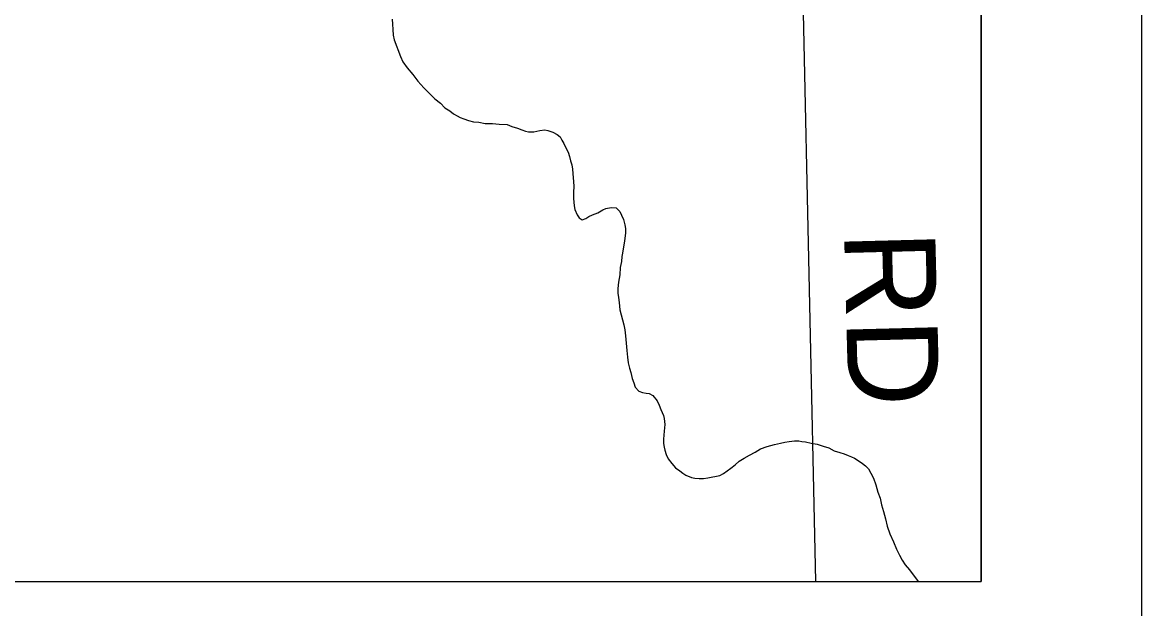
# Model space of a CAD drawing. Extents: x -59 to 82, y -3 to 49.
# Drawn here: x -48.696 to -47.998, y 42.474 to 42.84 of the extents above; entities that cross this region are included whole.
import ezdxf

# ---------------------------------------------------------------- set-up
doc = ezdxf.new("R2010")
doc.units = 0
for name, color, linetype in [('GM_X_Corporation', 7, 'Continuous'), ('GM_X_County_Road', 7, 'Continuous'), ('GM_X_County_Road_Text', 7, 'Continuous'), ('GM_X_Minor_River', 7, 'Continuous'), ('SH_Data', 7, 'Continuous')]:
    doc.layers.add(name, color=color, linetype=linetype)

msp = doc.modelspace()

# ---------------------------------------------------------------- linework, layer by layer
at = {"layer": 'GM_X_Corporation'}
for p, q in [((-48.09799, 42.49125), (-48.09799, 49.29125)), ((-48.09799, 42.49125), (-48.09799, 46.29445)), ((-54.89799, 42.49125), (-48.09799, 42.49125)), ((-49.66963, 42.49125), (-48.09799, 42.49125))]:
    msp.add_line(p, q, dxfattribs=at)
at = {"layer": 'GM_X_County_Road'}
msp.add_line((-48.22596, 43.60749), (-48.20125, 42.49125), dxfattribs=at)
at = {"layer": 'GM_X_Minor_River'}
for p, q in [((-48.46521, 42.84174), (-48.46518, 42.83869)), ((-48.46518, 42.83869), (-48.46478, 42.83527)), ((-48.46478, 42.83527), (-48.46475, 42.83185)), ((-48.46475, 42.83185), (-48.46397, 42.82882)), ((-48.46397, 42.82882), (-48.46009, 42.81858)), ((-48.46009, 42.81858), (-48.45854, 42.81517)), ((-48.45854, 42.81517), (-48.45585, 42.81139)), ((-48.45585, 42.81139), (-48.4524, 42.80723)), ((-48.4524, 42.80723), (-48.44933, 42.80307)), ((-48.44933, 42.80307), (-48.4455, 42.79891)), ((-48.4455, 42.79891), (-48.44205, 42.79552)), ((-48.44205, 42.79552), (-48.43861, 42.79212)), ((-48.43861, 42.79212), (-48.43517, 42.78948)), ((-48.43517, 42.78948), (-48.43249, 42.78646)), ((-48.43249, 42.78646), (-48.42943, 42.78458)), ((-48.42943, 42.78458), (-48.42714, 42.78269)), ((-48.42714, 42.78269), (-48.42485, 42.78157)), ((-48.42485, 42.78157), (-48.42295, 42.78044)), ((-48.42295, 42.78044), (-48.42066, 42.7797)), ((-48.42066, 42.7797), (-48.41762, 42.77858)), ((-48.41762, 42.77858), (-48.41457, 42.77784)), ((-48.41457, 42.77784), (-48.41115, 42.77748)), ((-48.41115, 42.77748), (-48.40735, 42.77675)), ((-48.40735, 42.77675), (-48.40279, 42.77678)), ((-48.40279, 42.77678), (-48.39861, 42.77643)), ((-48.39861, 42.77643), (-48.39367, 42.77609)), ((-48.39367, 42.77609), (-48.39063, 42.77497)), ((-48.39063, 42.77497), (-48.3872, 42.77385)), ((-48.3872, 42.77385), (-48.38453, 42.77273)), ((-48.38453, 42.77273), (-48.38225, 42.77198)), ((-48.37693, 42.77164), (-48.37314, 42.77243)), ((-48.37314, 42.77243), (-48.3701, 42.77283)), ((-48.3701, 42.77283), (-48.3682, 42.77246)), ((-48.3682, 42.77246), (-48.36516, 42.77134)), ((-48.38225, 42.77198), (-48.38035, 42.77162)), ((-48.38035, 42.77162), (-48.37693, 42.77164)), ((-48.36516, 42.77134), (-48.36249, 42.76984)), ((-48.36249, 42.76984), (-48.36058, 42.76834)), ((-48.36058, 42.76834), (-48.35942, 42.76644)), ((-48.35942, 42.76644), (-48.35826, 42.76417)), ((-48.35826, 42.76417), (-48.35672, 42.76114)), ((-48.35672, 42.76114), (-48.35556, 42.75887)), ((-48.35556, 42.75887), (-48.35478, 42.75621)), ((-48.35478, 42.75621), (-48.354, 42.75355)), ((-48.354, 42.75355), (-48.35322, 42.7509)), ((-48.35322, 42.7509), (-48.35282, 42.74824)), ((-48.35282, 42.74824), (-48.35197, 42.7376)), ((-48.35197, 42.7376), (-48.35232, 42.7338)), ((-48.35232, 42.7338), (-48.35229, 42.72999)), ((-48.35229, 42.72999), (-48.35188, 42.72543)), ((-48.35188, 42.72543), (-48.35148, 42.72316)), ((-48.33401, 42.7229), (-48.33212, 42.72367)), ((-48.33212, 42.72367), (-48.32871, 42.72446)), ((-48.32871, 42.72446), (-48.32567, 42.7241)), ((-48.32567, 42.7241), (-48.32337, 42.72183)), ((-48.35148, 42.72316), (-48.34993, 42.71975)), ((-48.34993, 42.71975), (-48.34878, 42.71785)), ((-48.34878, 42.71785), (-48.34687, 42.71673)), ((-48.34687, 42.71673), (-48.3446, 42.7175)), ((-48.3446, 42.7175), (-48.34271, 42.71866)), ((-48.34271, 42.71866), (-48.34044, 42.71981)), ((-48.34044, 42.71981), (-48.33703, 42.72098)), ((-48.33703, 42.72098), (-48.33401, 42.7229)), ((-48.32337, 42.72183), (-48.32221, 42.71956)), ((-48.32221, 42.71956), (-48.32105, 42.71691)), ((-48.32105, 42.71691), (-48.32026, 42.71349)), ((-48.32026, 42.71349), (-48.31987, 42.71121)), ((-48.31987, 42.71121), (-48.31985, 42.70855)), ((-48.3202, 42.70513), (-48.32055, 42.70208)), ((-48.31985, 42.70855), (-48.3202, 42.70513)), ((-48.32164, 42.69599), (-48.32201, 42.69371)), ((-48.32129, 42.69866), (-48.32164, 42.69599)), ((-48.32055, 42.70208), (-48.32129, 42.69866)), ((-48.32236, 42.69067), (-48.32309, 42.68686)), ((-48.32201, 42.69371), (-48.32236, 42.69067)), ((-48.32343, 42.6823), (-48.32415, 42.67773)), ((-48.32309, 42.68686), (-48.32343, 42.6823)), ((-48.32415, 42.67773), (-48.32451, 42.67392)), ((-48.32451, 42.67392), (-48.32448, 42.67088)), ((-48.32448, 42.67088), (-48.32408, 42.66822)), ((-48.32408, 42.66822), (-48.32368, 42.66519)), ((-48.32368, 42.66519), (-48.32326, 42.66063)), ((-48.32326, 42.66063), (-48.3209, 42.65114)), ((-48.3209, 42.65114), (-48.32012, 42.6481)), ((-48.32012, 42.6481), (-48.31971, 42.64431)), ((-48.31971, 42.64431), (-48.31929, 42.63974)), ((-48.31929, 42.63974), (-48.31888, 42.63519)), ((-48.31888, 42.63519), (-48.31846, 42.63101)), ((-48.31846, 42.63101), (-48.31806, 42.62759)), ((-48.31806, 42.62759), (-48.31727, 42.62417)), ((-48.31727, 42.62417), (-48.31649, 42.62152)), ((-48.31649, 42.62152), (-48.31609, 42.61962)), ((-48.31609, 42.61962), (-48.3157, 42.61772)), ((-48.3157, 42.61772), (-48.31454, 42.61507)), ((-48.31454, 42.61507), (-48.31376, 42.61241)), ((-48.31376, 42.61241), (-48.31146, 42.60977)), ((-48.31146, 42.60977), (-48.30917, 42.60902)), ((-48.30917, 42.60902), (-48.30689, 42.60866)), ((-48.30689, 42.60866), (-48.30499, 42.60829)), ((-48.30499, 42.60829), (-48.3027, 42.60717)), ((-48.3027, 42.60717), (-48.30002, 42.60377)), ((-48.30002, 42.60377), (-48.29886, 42.60111)), ((-48.29886, 42.60111), (-48.2977, 42.59846)), ((-48.2977, 42.59846), (-48.29692, 42.59657)), ((-48.29692, 42.59657), (-48.29615, 42.59467)), ((-48.29615, 42.59467), (-48.29575, 42.59277)), ((-48.29575, 42.59277), (-48.29534, 42.58897)), ((-48.29569, 42.58479), (-48.29603, 42.57984)), ((-48.29534, 42.58897), (-48.29569, 42.58479)), ((-48.29603, 42.57984), (-48.29601, 42.57718)), ((-48.29601, 42.57718), (-48.29561, 42.57491)), ((-48.2269, 42.57653), (-48.2231, 42.57732)), ((-48.2231, 42.57732), (-48.22045, 42.5781)), ((-48.22045, 42.5781), (-48.21779, 42.5785)), ((-48.21779, 42.5785), (-48.21438, 42.5789)), ((-48.21438, 42.5789), (-48.21172, 42.57892)), ((-48.21172, 42.57892), (-48.20982, 42.57855)), ((-48.20982, 42.57855), (-48.20754, 42.57819)), ((-48.20754, 42.57819), (-48.20412, 42.57745)), ((-48.20412, 42.57745), (-48.20031, 42.57672)), ((-48.29561, 42.57491), (-48.29522, 42.57301)), ((-48.29522, 42.57301), (-48.29443, 42.57035)), ((-48.29443, 42.57035), (-48.29327, 42.5677)), ((-48.24581, 42.56803), (-48.24241, 42.56996)), ((-48.24241, 42.56996), (-48.23901, 42.57188)), ((-48.23901, 42.57188), (-48.23561, 42.57381)), ((-48.23561, 42.57381), (-48.23144, 42.57536)), ((-48.23144, 42.57536), (-48.2269, 42.57653)), ((-48.20031, 42.57672), (-48.19651, 42.57561)), ((-48.19651, 42.57561), (-48.19308, 42.57449)), ((-48.19308, 42.57449), (-48.18965, 42.57261)), ((-48.18965, 42.57261), (-48.18622, 42.5715)), ((-48.18622, 42.5715), (-48.18356, 42.57075)), ((-48.18356, 42.57075), (-48.18089, 42.56963)), ((-48.29327, 42.5677), (-48.29097, 42.56467)), ((-48.29097, 42.56467), (-48.28867, 42.56203)), ((-48.25411, 42.56189), (-48.25147, 42.56381)), ((-48.25147, 42.56381), (-48.24883, 42.56611)), ((-48.24883, 42.56611), (-48.24581, 42.56803)), ((-48.18089, 42.56963), (-48.17899, 42.56889)), ((-48.17899, 42.56889), (-48.17708, 42.56814)), ((-48.17708, 42.56814), (-48.17403, 42.56626)), ((-48.17403, 42.56626), (-48.17212, 42.56475)), ((-48.17212, 42.56475), (-48.17021, 42.56325)), ((-48.17021, 42.56325), (-48.16829, 42.56136)), ((-48.28867, 42.56203), (-48.286, 42.56015)), ((-48.286, 42.56015), (-48.28409, 42.55864)), ((-48.28409, 42.55864), (-48.28218, 42.55751)), ((-48.28218, 42.55751), (-48.27875, 42.55602)), ((-48.27875, 42.55602), (-48.27647, 42.55565)), ((-48.26849, 42.55571), (-48.26091, 42.55728)), ((-48.26091, 42.55728), (-48.25865, 42.55844)), ((-48.25865, 42.55844), (-48.25411, 42.56189)), ((-48.16829, 42.56136), (-48.16676, 42.55871)), ((-48.16676, 42.55871), (-48.16521, 42.55568)), ((-48.27647, 42.55565), (-48.27381, 42.55529)), ((-48.27381, 42.55529), (-48.27115, 42.55531)), ((-48.27115, 42.55531), (-48.26849, 42.55571)), ((-48.16521, 42.55568), (-48.16366, 42.55151)), ((-48.16366, 42.55151), (-48.16248, 42.54695)), ((-48.16248, 42.54695), (-48.16093, 42.54317)), ((-48.16093, 42.54317), (-48.16014, 42.53899)), ((-48.16014, 42.53899), (-48.15897, 42.53481)), ((-48.15897, 42.53481), (-48.15779, 42.53026)), ((-48.15779, 42.53026), (-48.15662, 42.52571)), ((-48.15662, 42.52571), (-48.15506, 42.52078)), ((-48.15506, 42.52078), (-48.15274, 42.51585)), ((-48.15274, 42.51585), (-48.15081, 42.5113)), ((-48.15081, 42.5113), (-48.14888, 42.50752)), ((-48.14888, 42.50752), (-48.14733, 42.50449)), ((-48.14733, 42.50449), (-48.14541, 42.50146)), ((-48.14541, 42.50146), (-48.14273, 42.49844)), ((-48.14273, 42.49844), (-48.13725, 42.49125))]:
    msp.add_line(p, q, dxfattribs=at)
at = {"layer": 'SH_Data'}
for p, q in [((-47.99799, 49.39125), (-47.99799, 42.39125)), ((-48.09799, 49.29125), (-48.09799, 42.49125)), ((-54.89799, 42.49125), (-48.09799, 42.49125))]:
    msp.add_line(p, q, dxfattribs=at)

# ---------------------------------------------------------------- texts
at = {"layer": 'GM_X_County_Road_Text'}
msp.add_text('RD', height=0.056818, rotation=271.48252, dxfattribs=at).set_placement((-48.18355, 42.70931))

doc.saveas('drawing.dxf')
